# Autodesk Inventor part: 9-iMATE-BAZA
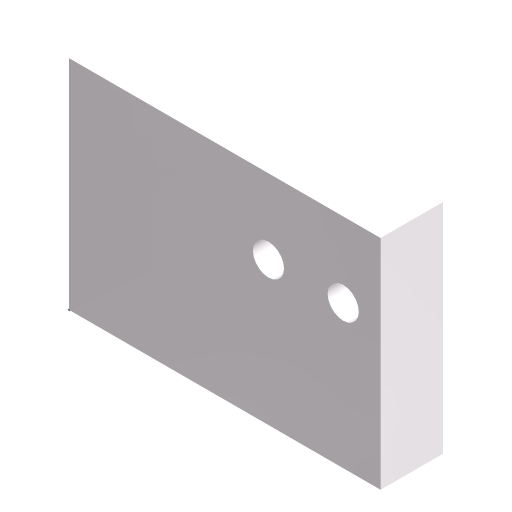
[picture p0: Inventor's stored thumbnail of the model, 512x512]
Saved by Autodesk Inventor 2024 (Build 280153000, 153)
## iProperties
Category: TEST
Company: ATC
Created: 2023-03
Part Number: 9-iMATE-BAZA
Document SubType Name: Modeling
Designer: Andrzej Jaskulski
Manufacturer: Standard
Standards Organization: Custom
Material: Kurs-AJ
Density: 1 g/cm^3
Appearance: Kurs-AJ
Checked By: A.J.
Engr Approved By: Andrzej Jaskulski
Mfg Approved By: Andrzej Jaskulski
Authority: A.J.
Gb: 805,00000 mm
Hb: 535,00000 mm
Gogz: 24,00000 mm
Hogz: 14,00000 mm
Hoz: 24,00000 mm
Gozz: 12,00000 mm
FiStd: 10,00000 mm
Sb: 1310,00000 mm
m3: m3
Szer: 20,00000 mm
Title: A.J.: Kurs R2024-MEP
Author: Andrzej Jaskulski
Revision Number: 1/24
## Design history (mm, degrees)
sketch "Baza"
  geometry: L1 (0, 0)-(-100, 0); L2 (-100, 0)-(-100, 70); L3 (-100, 70)-(0, 70); L4 (0, 70)-(0, 0); C1 r 5 at (-64, 46); C2 r 5 at (-88, 46)
  constraints: 8 end point, 2 centre point, 2 perpendicular, 1 horizontal, 1 horizontal alignment, 1 parallel, 1 vertical alignment, 1 other
  dimensions: "d3" = 70 distance of L1.end L2.end; "d14" = 24 distance of C2.centre C1.centre; "d15" = 24 distance from line of C2.centre L3 (= Hoz); "d17" = 12 distance from line of C2.centre L2 (= Gozz); "d45" = 100 distance of L1.start L1.end
extrude "Korpus" new body sketch "Baza" distance "d20" = 20; taper "d21" = 0 deg
node "Bryła1"
node "Korpusy bryłowe"
node "Korpusy powierzchniowe"
other parameters: "Gb" = 805 [user parameter], "Hb" = 535 [user parameter], "Gogz" = 24 [user parameter], "Hogz" = 14 [user parameter], "Hoz" = 24 [user parameter; used in 1 equation term], "Gozz" = 12 [user parameter; used in 1 equation term], "FiStd" = 10 [user parameter], "Sb" = 1310 [user parameter], "Szer" = 20 (= d20) [user parameter], "d44" = 0
